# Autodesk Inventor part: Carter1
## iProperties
Shininess: 64.0
Length Units: 11269
Angle Units: 11279
Time Units: 11290
Mass Units: 11283
Length Display Precision: 3
Angle Display Precision: 2
Compacted: True
Part Number: Carter1
Document SubType Name: Modeling
Created: 2005-01
Material: Par défaut
Designer: Flavien MARTY
Density: 0.0
Volumn: 0.0
Area: 0.0
PropertySet Name: Model Information
Control State: 0
Master: False
Checked Out: False
Norme de conversion: STEP AP203
Nom du fichier: Carter1.STEP
Préprocesseur: SolidWorks 2001039
Postprocesseur: Build: Release: 6 RTM Build: 90b - Date: Tue 09/24/2002
Unités envoyées: MILLIMETERS
Incertitude: 0.0
Author: Flavien MARTY
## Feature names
1. Base1
